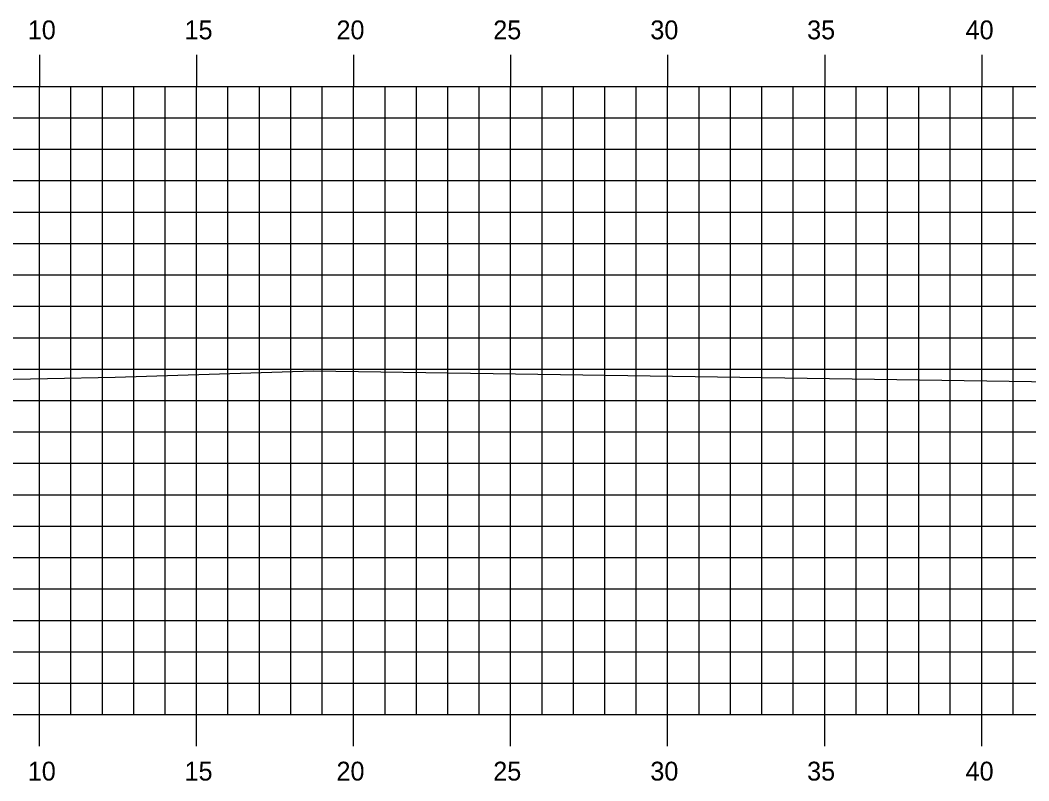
# Model space of a CAD drawing. Extents: x -161 to 764, y 111 to 210.
# Drawn here: x -78.31 to -46.19, y 176.32 to 200.54 of the extents above; entities that cross this region are included whole.
import ezdxf

# ---------------------------------------------------------------- set-up
doc = ezdxf.new("R2010")
doc.units = 0
for name, color, linetype in [('H_V ANNOTATION', 7, 'Continuous'), ('MAJOR', 7, 'Continuous'), ('MINOR', 7, 'Continuous'), ('S_Roadway_Centerline', 7, 'Continuous')]:
    doc.layers.add(name, color=color, linetype=linetype)

msp = doc.modelspace()

# ---------------------------------------------------------------- linework, layer by layer
at = {"layer": 'MAJOR'}
for p, q in [((-77.693, 199.435), (-77.693, 198.433)), ((-72.693, 199.435), (-72.693, 198.433)), ((-67.693, 199.435), (-67.693, 198.433)), ((-62.693, 199.435), (-62.693, 198.433)), ((-57.693, 199.435), (-57.693, 198.433)), ((-52.693, 199.435), (-52.693, 198.433)), ((-47.693, 199.435), (-47.693, 198.433)), ((-157.693, 198.433), (-17.693, 198.433)), ((-157.693, 198.433), (-17.693, 198.433)), ((-77.693, 178.433), (-77.693, 198.433)), ((-72.693, 178.433), (-72.693, 198.433)), ((-67.693, 178.433), (-67.693, 198.433)), ((-62.693, 178.433), (-62.693, 198.433)), ((-57.693, 178.433), (-57.693, 198.433)), ((-52.693, 178.433), (-52.693, 198.433)), ((-47.693, 178.433), (-47.693, 198.433)), ((-157.693, 193.433), (-17.693, 193.433)), ((-157.693, 188.433), (-17.693, 188.433)), ((-157.693, 183.433), (-17.693, 183.433)), ((-157.693, 178.433), (-17.693, 178.433)), ((-157.693, 178.433), (-17.693, 178.433)), ((-77.693, 177.431), (-77.693, 178.433)), ((-72.693, 177.431), (-72.693, 178.433)), ((-67.693, 177.431), (-67.693, 178.433)), ((-62.693, 177.431), (-62.693, 178.433)), ((-57.693, 177.431), (-57.693, 178.433)), ((-52.693, 177.431), (-52.693, 178.433)), ((-47.693, 177.431), (-47.693, 178.433))]:
    msp.add_line(p, q, dxfattribs=at)
at = {"layer": 'MINOR'}
for p, q in [((-76.693, 178.433), (-76.693, 198.433)), ((-75.693, 178.433), (-75.693, 198.433)), ((-74.693, 178.433), (-74.693, 198.433)), ((-73.693, 178.433), (-73.693, 198.433)), ((-71.693, 178.433), (-71.693, 198.433)), ((-70.693, 178.433), (-70.693, 198.433)), ((-69.693, 178.433), (-69.693, 198.433)), ((-68.693, 178.433), (-68.693, 198.433)), ((-66.693, 178.433), (-66.693, 198.433)), ((-65.693, 178.433), (-65.693, 198.433)), ((-64.693, 178.433), (-64.693, 198.433)), ((-63.693, 178.433), (-63.693, 198.433)), ((-61.693, 178.433), (-61.693, 198.433)), ((-60.693, 178.433), (-60.693, 198.433)), ((-59.693, 178.433), (-59.693, 198.433)), ((-58.693, 178.433), (-58.693, 198.433)), ((-56.693, 178.433), (-56.693, 198.433)), ((-55.693, 178.433), (-55.693, 198.433)), ((-54.693, 178.433), (-54.693, 198.433)), ((-53.693, 178.433), (-53.693, 198.433)), ((-51.693, 178.433), (-51.693, 198.433)), ((-50.693, 178.433), (-50.693, 198.433)), ((-49.693, 178.433), (-49.693, 198.433)), ((-48.693, 178.433), (-48.693, 198.433)), ((-46.693, 178.433), (-46.693, 198.433)), ((-157.693, 197.433), (-17.693, 197.433)), ((-157.693, 196.433), (-17.693, 196.433)), ((-157.693, 195.433), (-17.693, 195.433)), ((-157.693, 194.433), (-17.693, 194.433)), ((-157.693, 192.433), (-17.693, 192.433)), ((-157.693, 191.433), (-17.693, 191.433)), ((-157.693, 190.433), (-17.693, 190.433)), ((-157.693, 189.433), (-17.693, 189.433)), ((-157.693, 187.433), (-17.693, 187.433)), ((-157.693, 186.433), (-17.693, 186.433)), ((-157.693, 185.433), (-17.693, 185.433)), ((-157.693, 184.433), (-17.693, 184.433)), ((-157.693, 182.433), (-17.693, 182.433)), ((-157.693, 181.433), (-17.693, 181.433)), ((-157.693, 180.433), (-17.693, 180.433)), ((-157.693, 179.433), (-17.693, 179.433))]:
    msp.add_line(p, q, dxfattribs=at)
at = {"layer": 'S_Roadway_Centerline'}
msp.add_lwpolyline([(-157.693, 186.896), (-152.22, 186.735), (-150.498, 186.807), (-148.901, 186.975), (-141.893, 187.734), (-139.882, 188.09), (-132.124, 189.256), (-128.171, 189.315), (-121.467, 188.992), (-115.974, 188.872), (-110.769, 188.6), (-96.239, 188.433), (-93.99, 188.538), (-87.1, 188.918), (-86.065, 188.968), (-75.289, 189.172), (-68.973, 189.373), (-42.532, 188.98), (-34.493, 188.828), (-32.191, 188.81), (-29.47, 188.805), (-17.693, 188.431)], dxfattribs=at)

# ---------------------------------------------------------------- texts
at = {"layer": 'H_V ANNOTATION'}
for s, p in [('10', (-78.068, 199.933)), ('15', (-73.076, 199.933)), ('20', (-68.239, 199.933)), ('25', (-63.247, 199.933)), ('30', (-58.245, 199.933)), ('35', (-53.253, 199.933)), ('40', (-48.207, 199.933)), ('10', (-78.068, 176.333)), ('15', (-73.076, 176.333)), ('20', (-68.239, 176.333)), ('25', (-63.247, 176.333)), ('30', (-58.245, 176.333)), ('35', (-53.253, 176.333)), ('40', (-48.207, 176.333))]:
    msp.add_text(s, height=0.6, rotation=360, dxfattribs=at).set_placement(p)

doc.saveas('drawing.dxf')
